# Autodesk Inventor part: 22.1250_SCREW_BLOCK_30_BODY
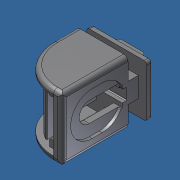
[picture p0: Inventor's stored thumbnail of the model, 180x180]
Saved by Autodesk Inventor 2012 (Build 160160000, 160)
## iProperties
Created: 2016-06
Part Number: 22.1250_SCREW_BLOCK_30_BODY
Material: ABS Plastic
Document SubType Name: Modeling
Designer: Admin
Density: 1.06 g/cm^3
Mass: 5.06959 g
Surface Area: 48.0858 cm^2
Volume: 4.78263 cm^3
Author: Admin
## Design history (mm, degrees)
feature "Base1"
body "Solid1"
